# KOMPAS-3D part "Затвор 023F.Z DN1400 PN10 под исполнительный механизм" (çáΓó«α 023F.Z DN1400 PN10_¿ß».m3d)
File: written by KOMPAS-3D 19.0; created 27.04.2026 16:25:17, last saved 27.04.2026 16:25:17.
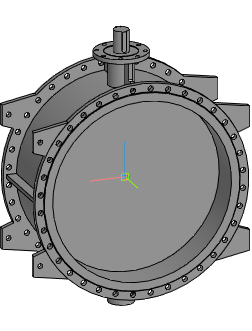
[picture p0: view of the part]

Document properties: Автор: Евгений; Полное имя файла: Z:\3.Личные\kachalov\3d для проектировщиков\1.7 Тип 023F.Z Затвор дисковый поворотный фланцевый с двумя эксцентриками\Затвор 023F.Z DN200-DN1600_исп\_stp_Затвор 023F.Z DN200-DN1600_исп\Затвор 023F.Z DN1400 PN10_исп.m3d

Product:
- Part/product: Затвор 023F.Z DN1400 PN10 под исполнительный механизм

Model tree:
1. Операция без истории:1  (labels: Затвор 023F.Z DN1400 PN10 под исполнительный механизм)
